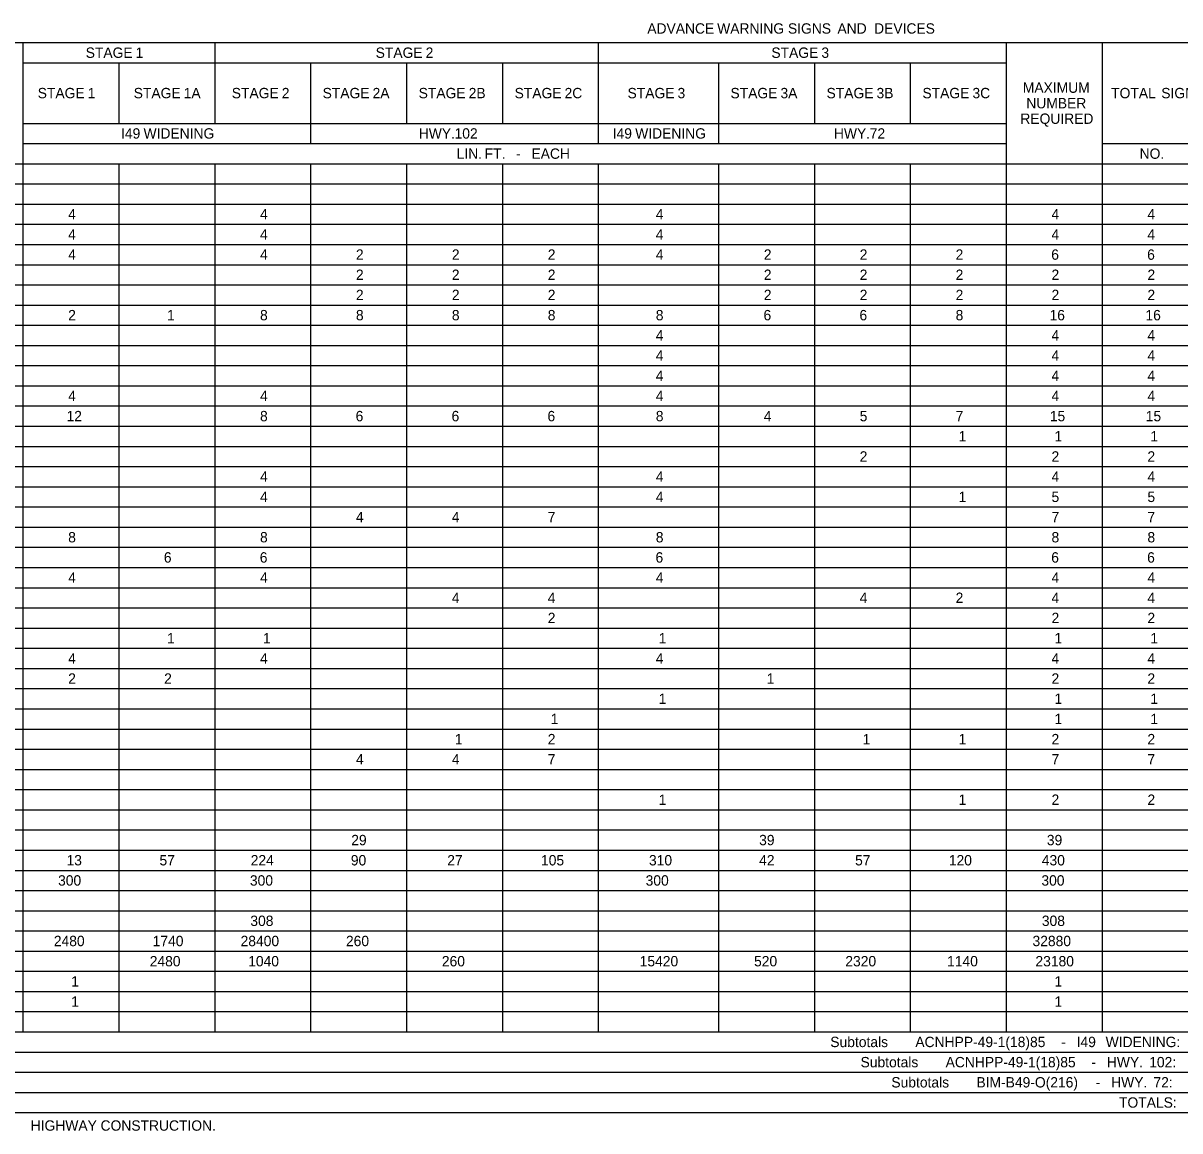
# Model space of a CAD drawing. Extents: x 1225909 to 1228704, y 151309 to 152305.
# Drawn here: x 1226842.6 to 1227205.7, y 151938 to 152285.7 of the extents above; entities that cross this region are included whole.
import ezdxf

# ---------------------------------------------------------------- set-up
doc = ezdxf.new("R2010")
doc.units = 0
doc.layers.add('R_Dimension', color=7, linetype='Continuous')

msp = doc.modelspace()

# ---------------------------------------------------------------- linework, layer by layer
at = {"layer": 'R_Dimension'}
for p, q in [((1226577.42, 152279.62), (1227591.1, 152279.62)), ((1226842.64, 151969.08), (1226842.64, 152279.62)), ((1226902.85, 152254.27), (1226902.85, 152279.62)), ((1227023.26, 152247.93), (1227023.26, 152279.62)), ((1227151.28, 151969.08), (1227151.28, 152279.62)), ((1227181.38, 151969.08), (1227181.38, 152279.62)), ((1226842.64, 152273.28), (1227151.28, 152273.28)), ((1226872.75, 152254.27), (1226872.75, 152273.28)), ((1226932.95, 152247.93), (1226932.95, 152273.28)), ((1226963.06, 152254.27), (1226963.06, 152273.28)), ((1226993.16, 152254.27), (1226993.16, 152273.28)), ((1227060.97, 152247.93), (1227060.97, 152273.28)), ((1227091.07, 152254.27), (1227091.07, 152273.28)), ((1227121.18, 152254.27), (1227121.18, 152273.28)), ((1226842.64, 152254.27), (1227151.28, 152254.27)), ((1226842.64, 152247.93), (1227151.28, 152247.93)), ((1227181.38, 152247.93), (1227591.1, 152247.93)), ((1226577.42, 152241.6), (1227591.1, 152241.6)), ((1226872.75, 151969.08), (1226872.75, 152241.6)), ((1226902.85, 151969.08), (1226902.85, 152241.6)), ((1226932.95, 151969.08), (1226932.95, 152241.6)), ((1226963.06, 151969.08), (1226963.06, 152241.6)), ((1226993.16, 151969.08), (1226993.16, 152241.6)), ((1227023.26, 151969.08), (1227023.26, 152241.6)), ((1227060.97, 151969.08), (1227060.97, 152241.6)), ((1227091.07, 151969.08), (1227091.07, 152241.6)), ((1227121.18, 151969.08), (1227121.18, 152241.6)), ((1227151.28, 152241.6), (1227591.1, 152241.6)), ((1226577.42, 152235.26), (1227591.1, 152235.26)), ((1226577.42, 152228.92), (1227591.1, 152228.92)), ((1226577.42, 152222.58), (1227591.1, 152222.58)), ((1226577.42, 152216.25), (1227591.1, 152216.25)), ((1226577.42, 152209.91), (1227591.1, 152209.91)), ((1226577.42, 152203.57), (1227591.1, 152203.57)), ((1226577.42, 152197.23), (1227591.1, 152197.23)), ((1226577.42, 152190.9), (1227591.1, 152190.9)), ((1226577.42, 152184.56), (1227591.1, 152184.56)), ((1226577.42, 152178.22), (1227591.1, 152178.22)), ((1226577.42, 152171.88), (1227591.1, 152171.88)), ((1226577.42, 152165.55), (1227591.1, 152165.55)), ((1226577.42, 152159.21), (1227591.1, 152159.21)), ((1226577.42, 152152.87), (1227591.1, 152152.87)), ((1226577.42, 152146.53), (1227591.1, 152146.53)), ((1226577.42, 152140.2), (1227591.1, 152140.2)), ((1226577.42, 152133.86), (1227591.1, 152133.86)), ((1226577.42, 152127.52), (1227591.1, 152127.52)), ((1226577.42, 152121.18), (1227591.1, 152121.18)), ((1226577.42, 152114.85), (1227591.1, 152114.85)), ((1226577.42, 152108.51), (1227591.1, 152108.51)), ((1226577.42, 152102.17), (1227591.1, 152102.17)), ((1226577.42, 152095.83), (1227591.1, 152095.83)), ((1226577.42, 152089.5), (1227591.1, 152089.5)), ((1226577.42, 152083.16), (1227591.1, 152083.16)), ((1226577.42, 152076.82), (1227591.1, 152076.82)), ((1226577.42, 152070.48), (1227591.1, 152070.48)), ((1226577.42, 152064.15), (1227591.1, 152064.15)), ((1226577.42, 152057.81), (1227591.1, 152057.81)), ((1226577.42, 152051.47), (1227591.1, 152051.47)), ((1226577.42, 152045.13), (1227591.1, 152045.13)), ((1226577.42, 152038.8), (1227591.1, 152038.8)), ((1226577.42, 152032.46), (1227591.1, 152032.46)), ((1226577.42, 152026.12), (1227591.1, 152026.12)), ((1226577.42, 152019.78), (1227591.1, 152019.78)), ((1226577.42, 152013.45), (1227591.1, 152013.45)), ((1226577.42, 152007.11), (1227591.1, 152007.11)), ((1226577.42, 152000.77), (1227591.1, 152000.77)), ((1226577.42, 151994.43), (1227591.1, 151994.43)), ((1226577.42, 151988.1), (1227591.1, 151988.1)), ((1226577.42, 151981.76), (1227591.1, 151981.76)), ((1226577.42, 151975.42), (1227591.1, 151975.42)), ((1226577.42, 151969.08), (1227591.1, 151969.08)), ((1226577.42, 151962.75), (1227591.1, 151962.75)), ((1226577.42, 151956.41), (1227591.1, 151956.41)), ((1226577.42, 151950.07), (1227591.1, 151950.07)), ((1226577.42, 151943.73), (1227591.1, 151943.73))]:
    msp.add_line(p, q, dxfattribs=at)

# ---------------------------------------------------------------- texts
for s, p in [('ADVANCE', (1227038.53, 152282.43)), (' WARNING', (1227059.26, 152282.43)), (' SIGNS', (1227081.47, 152282.43)), (' AND', (1227097.01, 152282.43)), (' DEVICES', (1227108.52, 152282.43)), ('STAGE', (1226862.26, 152274.83)), (' 1', (1226876.74, 152274.83)), ('STAGE', (1226953.27, 152274.83)), (' 2', (1226967.75, 152274.83)), ('STAGE', (1227077.48, 152274.83)), (' 3', (1227091.97, 152274.83)), ('MAXIMUM', (1227156.4, 152263.86)), ('STAGE', (1226847.2, 152262.15)), (' 1', (1226861.69, 152262.15)), ('STAGE', (1226877.33, 152262.15)), (' 1A', (1226891.82, 152262.15)), ('STAGE', (1226908.11, 152262.15)), (' 2', (1226922.6, 152262.15)), ('STAGE', (1226936.62, 152262.15)), (' 2A', (1226951.1, 152262.15)), ('STAGE', (1226966.77, 152262.15)), (' 2B', (1226981.26, 152262.15)), ('STAGE', (1226996.88, 152262.15)), (' 2C', (1227011.36, 152262.15)), ('STAGE', (1227032.33, 152262.15)), (' 3', (1227046.81, 152262.15)), ('STAGE', (1227064.64, 152262.15)), (' 3A', (1227079.12, 152262.15)), ('STAGE', (1227094.79, 152262.15)), (' 3B', (1227109.27, 152262.15)), ('STAGE', (1227124.89, 152262.15)), (' 3C', (1227139.38, 152262.15)), ('NUMBER', (1227157.49, 152258.98)), ('TOTAL', (1227184.12, 152262.15)), (' SIGNS', (1227198.65, 152262.15)), ('REQUIRED', (1227155.62, 152254.11)), ('I49', (1226873.35, 152249.48)), (' WIDENING', (1226879.21, 152249.48)), ('HWY.', (1226966.8, 152249.48)), (' 102', (1226976.83, 152249.48)), ('I49', (1227027.67, 152249.48)), (' WIDENING', (1227033.53, 152249.48)), ('HWY.', (1227097.11, 152249.48)), (' 72', (1227107.14, 152249.48)), ('LIN.', (1226978.7, 152243.14)), (' FT.', (1226986.28, 152243.14)), (' -', (1226996.13, 152243.14)), (' EACH', (1227000.97, 152243.14)), ('NO.', (1227193.06, 152243.14)), ('4', (1226856.77, 152224.13)), ('4', (1226916.98, 152224.13)), ('4', (1227041.2, 152224.13)), ('4', (1227165.41, 152224.13)), ('4', (1227195.51, 152224.13)), ('4', (1226856.77, 152217.79)), ('4', (1226916.98, 152217.79)), ('4', (1227041.2, 152217.79)), ('4', (1227165.41, 152217.79)), ('4', (1227195.51, 152217.79)), ('4', (1226856.77, 152211.45)), ('4', (1226916.98, 152211.45)), ('2', (1226947.08, 152211.45)), ('2', (1226977.19, 152211.45)), ('2', (1227007.29, 152211.45)), ('4', (1227041.2, 152211.45)), ('2', (1227075.1, 152211.45)), ('2', (1227105.2, 152211.45)), ('2', (1227135.31, 152211.45)), ('6', (1227165.32, 152211.45)), ('6', (1227195.42, 152211.45)), ('2', (1226947.08, 152205.12)), ('2', (1226977.19, 152205.12)), ('2', (1227007.29, 152205.12)), ('2', (1227075.1, 152205.12)), ('2', (1227105.2, 152205.12)), ('2', (1227135.31, 152205.12)), ('2', (1227165.41, 152205.12)), ('2', (1227195.51, 152205.12)), ('2', (1226947.08, 152198.78)), ('2', (1226977.19, 152198.78)), ('2', (1227007.29, 152198.78)), ('2', (1227075.1, 152198.78)), ('2', (1227105.2, 152198.78)), ('2', (1227135.31, 152198.78)), ('2', (1227165.41, 152198.78)), ('2', (1227195.51, 152198.78)), ('2', (1226856.77, 152192.44)), ('1', (1226887.8, 152192.44)), ('8', (1226916.98, 152192.44)), ('8', (1226947.08, 152192.44)), ('8', (1226977.19, 152192.44)), ('8', (1227007.29, 152192.44)), ('8', (1227041.2, 152192.44)), ('6', (1227075.01, 152192.44)), ('6', (1227105.12, 152192.44)), ('8', (1227135.31, 152192.44)), ('16', (1227164.78, 152192.44)), ('16', (1227194.89, 152192.44)), ('4', (1227041.2, 152186.1)), ('4', (1227165.41, 152186.1)), ('4', (1227195.51, 152186.1)), ('4', (1227041.2, 152179.77)), ('4', (1227165.41, 152179.77)), ('4', (1227195.51, 152179.77)), ('4', (1227041.2, 152173.43)), ('4', (1227165.41, 152173.43)), ('4', (1227195.51, 152173.43)), ('4', (1226856.77, 152167.09)), ('4', (1226916.98, 152167.09)), ('4', (1227041.2, 152167.09)), ('4', (1227165.41, 152167.09)), ('4', (1227195.51, 152167.09)), ('12', (1226856.24, 152160.75)), ('8', (1226916.98, 152160.75)), ('6', (1226946.99, 152160.75)), ('6', (1226977.1, 152160.75)), ('6', (1227007.2, 152160.75)), ('8', (1227041.2, 152160.75)), ('4', (1227075.1, 152160.75)), ('5', (1227105.2, 152160.75)), ('7', (1227135.31, 152160.75)), ('15', (1227164.87, 152160.75)), ('15', (1227194.98, 152160.75)), ('1', (1227136.23, 152154.42)), ('1', (1227166.33, 152154.42)), ('1', (1227196.44, 152154.42)), ('2', (1227105.2, 152148.08)), ('2', (1227165.41, 152148.08)), ('2', (1227195.51, 152148.08)), ('4', (1226916.98, 152141.74)), ('4', (1227041.2, 152141.74)), ('4', (1227165.41, 152141.74)), ('4', (1227195.51, 152141.74)), ('4', (1226916.98, 152135.4)), ('4', (1227041.2, 152135.4)), ('1', (1227136.23, 152135.4)), ('5', (1227165.41, 152135.4)), ('5', (1227195.51, 152135.4)), ('4', (1226947.08, 152129.07)), ('4', (1226977.19, 152129.07)), ('7', (1227007.29, 152129.07)), ('7', (1227165.41, 152129.07)), ('7', (1227195.51, 152129.07)), ('8', (1226856.77, 152122.73)), ('8', (1226916.98, 152122.73)), ('8', (1227041.2, 152122.73)), ('8', (1227165.41, 152122.73)), ('8', (1227195.51, 152122.73)), ('6', (1226886.79, 152116.39)), ('6', (1226916.89, 152116.39)), ('6', (1227041.11, 152116.39)), ('6', (1227165.32, 152116.39)), ('6', (1227195.42, 152116.39)), ('4', (1226856.77, 152110.05)), ('4', (1226916.98, 152110.05)), ('4', (1227041.2, 152110.05)), ('4', (1227165.41, 152110.05)), ('4', (1227195.51, 152110.05)), ('4', (1226977.19, 152103.72)), ('4', (1227007.29, 152103.72)), ('4', (1227105.2, 152103.72)), ('2', (1227135.31, 152103.72)), ('4', (1227165.41, 152103.72)), ('4', (1227195.51, 152103.72)), ('2', (1227007.29, 152097.38)), ('2', (1227165.41, 152097.38)), ('2', (1227195.51, 152097.38)), ('1', (1226887.8, 152091.04)), ('1', (1226917.9, 152091.04)), ('1', (1227042.12, 152091.04)), ('1', (1227166.33, 152091.04)), ('1', (1227196.44, 152091.04)), ('4', (1226856.77, 152084.7)), ('4', (1226916.98, 152084.7)), ('4', (1227041.2, 152084.7)), ('4', (1227165.41, 152084.7)), ('4', (1227195.51, 152084.7)), ('2', (1226856.77, 152078.37)), ('2', (1226886.88, 152078.37)), ('1', (1227076.02, 152078.37)), ('2', (1227165.41, 152078.37)), ('2', (1227195.51, 152078.37)), ('1', (1227042.12, 152072.03)), ('1', (1227166.33, 152072.03)), ('1', (1227196.44, 152072.03)), ('1', (1227008.21, 152065.69)), ('1', (1227166.33, 152065.69)), ('1', (1227196.44, 152065.69)), ('1', (1226978.11, 152059.35)), ('2', (1227007.29, 152059.35)), ('1', (1227106.13, 152059.35)), ('1', (1227136.23, 152059.35)), ('2', (1227165.41, 152059.35)), ('2', (1227195.51, 152059.35)), ('4', (1226947.08, 152053.02)), ('4', (1226977.19, 152053.02)), ('7', (1227007.29, 152053.02)), ('7', (1227165.41, 152053.02)), ('7', (1227195.51, 152053.02)), ('1', (1227042.12, 152040.34)), ('1', (1227136.23, 152040.34)), ('2', (1227165.41, 152040.34)), ('2', (1227195.51, 152040.34)), ('29', (1226945.61, 152027.67)), ('39', (1227073.63, 152027.67)), ('39', (1227163.94, 152027.67)), ('13', (1226856.24, 152021.33)), ('57', (1226885.42, 152021.33)), ('224', (1226914.06, 152021.33)), ('90', (1226945.48, 152021.33)), ('27', (1226975.73, 152021.33)), ('105', (1227005.17, 152021.33)), ('310', (1227039.06, 152021.33)), ('42', (1227073.64, 152021.33)), ('57', (1227103.75, 152021.33)), ('120', (1227133.17, 152021.33)), ('430', (1227162.35, 152021.33)), ('300', (1226853.59, 152014.99)), ('300', (1226913.8, 152014.99)), ('300', (1227038.01, 152014.99)), ('300', (1227162.23, 152014.99)), ('308', (1226913.94, 152002.32)), ('308', (1227162.37, 152002.32)), ('2480', (1226852.26, 151995.98)), ('1740', (1226883.28, 151995.98)), ('28400', (1226910.88, 151995.98)), ('260', (1226943.95, 151995.98)), ('32880', (1227159.44, 151995.98)), ('2480', (1226882.36, 151989.64)), ('1040', (1226913.26, 151989.64)), ('260', (1226974.05, 151989.64)), ('15420', (1227036.14, 151989.64)), ('520', (1227072.04, 151989.64)), ('2320', (1227100.69, 151989.64)), ('1140', (1227132.63, 151989.64)), ('23180', (1227160.36, 151989.64)), ('1', (1226857.7, 151983.3)), ('1', (1227166.33, 151983.3)), ('1', (1226857.7, 151976.97)), ('1', (1227166.33, 151976.97)), ('Subtotals', (1227095.97, 151964.29)), (' ACNHPP-49-1(18)85', (1227121.46, 151964.29)), (' -', (1227167.24, 151964.29)), (' I49', (1227172.08, 151964.29)), (' WIDENING:', (1227181.19, 151964.29)), ('Subtotals', (1227105.47, 151957.95)), (' ACNHPP-49-1(18)85', (1227130.96, 151957.95)), (' HWY.', (1227181.57, 151957.95)), (' 102:', (1227194.86, 151957.95)), (' -', (1227176.74, 151957.95)), ('Subtotals', (1227115.14, 151951.62)), (' BIM-B49-O(216)', (1227140.63, 151951.62)), (' HWY.', (1227182.91, 151951.62)), (' 72:', (1227196.19, 151951.62)), (' -', (1227178.07, 151951.62)), ('TOTALS:', (1227186.59, 151945.28)), (' HIGHWAY', (1226843.79, 151938.05)), (' CONSTRUCTION.', (1226865.72, 151938.05))]:
    msp.add_text(s, height=3.25, dxfattribs=at).set_placement(p)

doc.saveas('drawing.dxf')
